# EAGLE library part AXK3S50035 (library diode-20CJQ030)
Matsushita P6 NARROW-PITCH CONNECTORS FOR PC BOARDS 50Pin Socket NARROW-PITCH (0.6mm) CONNECTORS P6 SERIES FEATURES The product lineup consists of the low profile of: - 3 mm - 4 mm - 5 mm - 6 mm - 7 mm - 8 mm - 9 mm APPLICATIONS Small portable equipment, laptop computers, video equipment, radio communication, cellular telephones, etc. Please send any comments to: messi@users.sourceforge.net
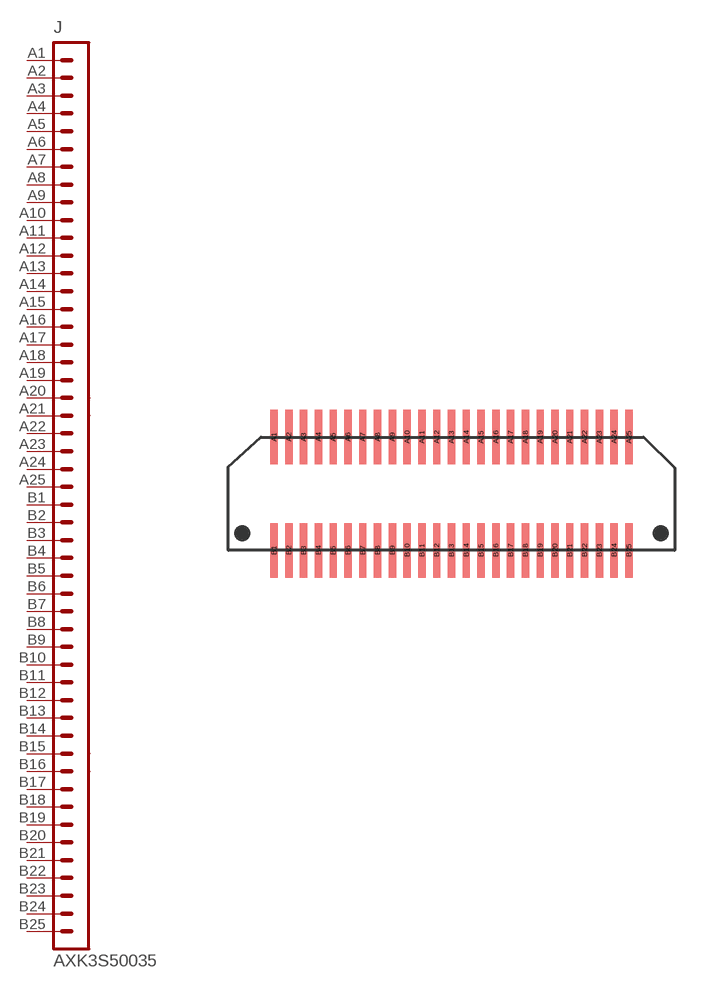
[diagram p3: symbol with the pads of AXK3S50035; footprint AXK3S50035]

Designator prefix J

## AXK3S50035  [AXK3S50035]
A1  1  pas
A2  2  pas
A3  3  pas
A4  4  pas
A5  5  pas
A6  6  pas
A7  7  pas
A8  8  pas
A9  9  pas
A10  10  pas
A11  11  pas
A12  12  pas
A13  13  pas
A14  14  pas
A15  15  pas
A16  16  pas
A17  17  pas
A18  18  pas
A19  19  pas
A20  20  pas
A21  21  pas
A22  22  pas
A23  23  pas
A24  24  pas
A25  25  pas
B1  26  pas
B2  27  pas
B3  28  pas
B4  29  pas
B5  30  pas
B6  31  pas
B7  32  pas
B8  33  pas
B9  34  pas
B10  35  pas
B11  36  pas
B12  37  pas
B13  38  pas
B14  39  pas
B15  40  pas
B16  41  pas
B17  42  pas
B18  43  pas
B19  44  pas
B20  45  pas
B21  46  pas
B22  47  pas
B23  48  pas
B24  49  pas
B25  50  pas

## Footprint AXK3S50035 (pad centres in mm)
Matsushita NARROW-PITCH CONNECTORS FOR PC BOARDS 50Pin Socket NARROW-PITCH (0.6mm) CONNECTORS P6 SERIES FEATURES The product lineup consists of the low profile of: - 3 mm - 4 mm - 5 mm - 6 mm - 7 mm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
smd 0.3 x 2.2: A1 -7.2,2.3; A2 -6.6,2.3; A3 -6,2.3; A4 -5.4,2.3; A5 -4.8,2.3; A6 -4.2,2.3; A7 -3.6,2.3; A8 -3,2.3; A9 -2.4,2.3; A10 -1.8,2.3; A11 -1.2,2.3; A12 -0.6,2.3; A13 0,2.3; A14 0.6,2.3; A15 1.2,2.3; A16 1.8,2.3; A17 2.4,2.3; A18 3,2.3; A19 3.6,2.3; A20 4.2,2.3; A21 4.8,2.3; A22 5.4,2.3; A23 6,2.3; A24 6.6,2.3; A25 7.2,2.3; B1 -7.2,-2.3; B2 -6.6,-2.3; B3 -6,-2.3; B4 -5.4,-2.3; B5 -4.8,-2.3; B6 -4.2,-2.3; B7 -3.6,-2.3; B8 -3,-2.3; B9 -2.4,-2.3; B10 -1.8,-2.3; B11 -1.2,-2.3; B12 -0.6,-2.3; B13 0,-2.3; B14 0.6,-2.3; B15 1.2,-2.3; B16 1.8,-2.3; B17 2.4,-2.3; B18 3,-2.3; B19 3.6,-2.3; B20 4.2,-2.3; B21 4.8,-2.3; B22 5.4,-2.3; B23 6,-2.3; B24 6.6,-2.3; B25 7.2,-2.3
